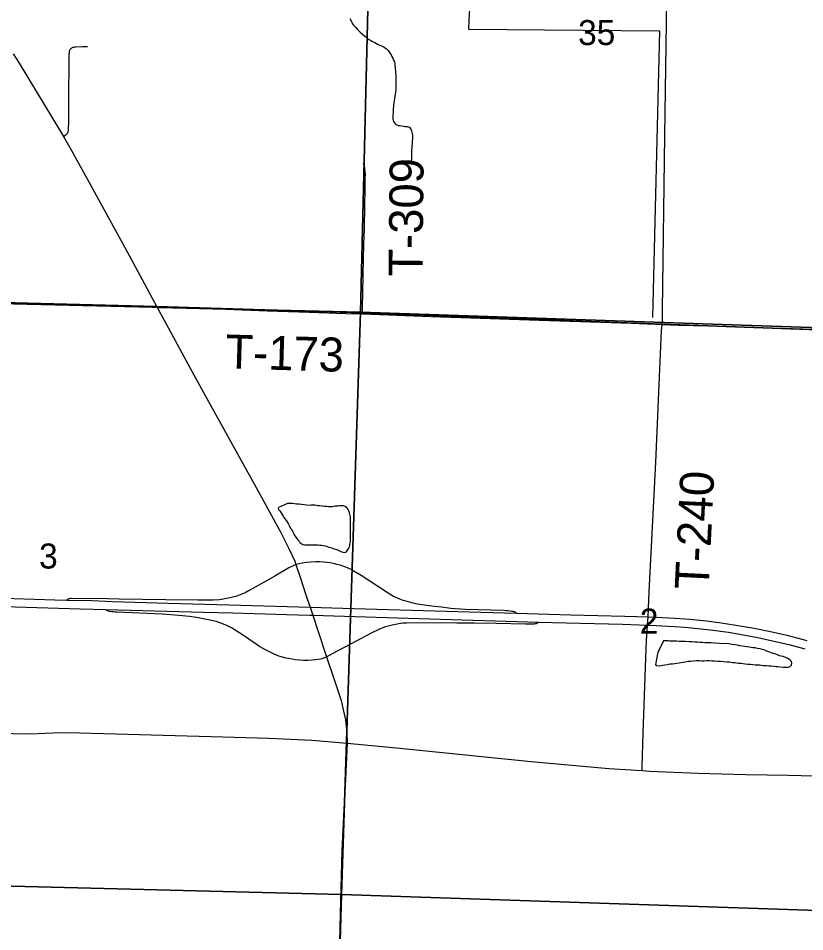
# Model space of a CAD drawing. Extents: x 0 to 68, y 0 to 52.9.
# Drawn here: x 29.418 to 30.689, y 16.814 to 18.289 of the extents above; entities that cross this region are included whole.
import ezdxf

# ---------------------------------------------------------------- set-up
doc = ezdxf.new("R2010")
doc.units = 0
for name, color, linetype in [('Default', 7, 'Continuous'), ('GM_X_County_Road', 7, 'Continuous'), ('GM_X_Minor_Lake', 7, 'Continuous'), ('GM_X_Minor_River', 7, 'Continuous'), ('GM_X_State_Route', 7, 'Continuous'), ('GM_X_Township', 7, 'Continuous'), ('GM_X_Township_Road', 7, 'Continuous'), ('GM_X_Township_Road_Text', 7, 'Continuous')]:
    doc.layers.add(name, color=color, linetype=linetype)

msp = doc.modelspace()

# ---------------------------------------------------------------- linework, layer by layer
at = {"layer": 'Default'}
for points in [[(29.9941, 18.7705), (29.9713, 17.8144), (29.0063, 17.8378), (29.0222, 18.7966)], [(30.9488, 18.7396), (30.9354, 17.7816), (29.9713, 17.8144), (29.9941, 18.7705)], [(28.9884, 17.8384), (29.0063, 17.8378), (29.9713, 17.8144), (29.9405, 16.874), (28.9602, 16.899)], [(29.9713, 17.8144), (30.9354, 17.7816), (30.9018, 16.8419), (29.9405, 16.874)], [(28.9602, 16.899), (29.9405, 16.874), (29.9124, 15.9054), (28.9346, 15.9322)], [(29.9405, 16.874), (30.9018, 16.8419), (30.8795, 15.8743), (29.9124, 15.9054)]]:
    msp.add_lwpolyline(points, close=True, dxfattribs=at)
for points in [[(29.8667, 17.4068), (29.8611, 17.4042), (29.8556, 17.4014), (29.8329, 17.3884), (29.8155, 17.3784), (29.7971, 17.368), (29.7916, 17.3651), (29.7847, 17.3615), (29.7795, 17.3592), (29.7751, 17.3574), (29.7696, 17.3556), (29.7649, 17.3543), (29.7601, 17.353), (29.7548, 17.3519), (29.7498, 17.3509), (29.7436, 17.3502), (29.733, 17.3495), (29.7084, 17.3494), (29.6565, 17.3498), (29.5815, 17.3511), (29.5623, 17.3515), (29.5042, 17.3522), (29.5035, 17.3521), (29.5028, 17.3521), (29.5021, 17.352), (29.5012, 17.3518), (29.5003, 17.3516), (29.4998, 17.3514), (29.4993, 17.3512), (29.4987, 17.3509), (29.498, 17.3506), (29.4974, 17.3501), (29.497, 17.3495)], [(30.2229, 17.3285), (30.2225, 17.3291), (30.222, 17.3296), (30.2215, 17.3299), (30.2207, 17.3303), (30.2196, 17.3306), (30.218, 17.3309), (30.2154, 17.3313), (30.2127, 17.3316), (30.2094, 17.332), (30.2063, 17.3323), (30.2027, 17.3325), (30.1404, 17.3343), (30.1328, 17.3347), (30.1229, 17.3355), (30.1169, 17.3361), (30.1021, 17.3379), (30.0908, 17.3392), (30.0745, 17.3415), (30.0629, 17.3431), (30.0543, 17.3449), (30.0466, 17.3471), (30.0403, 17.349), (30.0345, 17.3512), (30.0245, 17.3555), (30.0159, 17.3607), (29.9721, 17.3895), (29.9623, 17.3953), (29.9561, 17.3989), (29.9476, 17.4025), (29.9381, 17.4058), (29.9332, 17.4072), (29.9298, 17.408), (29.925, 17.409), (29.9219, 17.4096), (29.917, 17.4104), (29.9118, 17.4108), (29.9052, 17.4111), (29.899, 17.4112), (29.8911, 17.4108), (29.884, 17.4101), (29.8772, 17.409), (29.872, 17.4079), (29.8667, 17.4068)], [(29.5602, 17.3342), (29.5608, 17.3335), (29.5616, 17.3329), (29.5623, 17.3325), (29.5637, 17.3321), (29.5659, 17.3317), (29.5699, 17.3311), (29.5718, 17.3309), (29.5749, 17.3306), (29.5774, 17.3304), (29.6516, 17.3276), (29.6778, 17.3254), (29.6952, 17.3234), (29.7061, 17.3218), (29.7172, 17.3199), (29.7286, 17.3177), (29.7377, 17.3154), (29.7468, 17.3125), (29.7558, 17.3087), (29.7644, 17.3041), (29.7806, 17.2939), (29.8008, 17.2801), (29.8088, 17.2748), (29.817, 17.27), (29.8245, 17.2659), (29.8313, 17.2629), (29.8389, 17.2596), (29.8447, 17.2577), (29.8502, 17.2563), (29.8548, 17.2555), (29.866, 17.2536), (29.8729, 17.2531), (29.8792, 17.2528), (29.886, 17.2527), (29.8932, 17.253), (29.8984, 17.2534), (29.9026, 17.254), (29.9065, 17.2547), (29.9093, 17.2553), (29.9138, 17.257), (29.9164, 17.2581)], [(29.9164, 17.2581), (29.9247, 17.2629), (29.9668, 17.2848), (29.9889, 17.2968), (30.0012, 17.3025), (30.0116, 17.3067), (30.0222, 17.3097), (30.0329, 17.3118), (30.0393, 17.3127), (30.0457, 17.3129), (30.0891, 17.3132), (30.1268, 17.3129), (30.1553, 17.3127), (30.1905, 17.3122), (30.2385, 17.3111), (30.2427, 17.3111), (30.2453, 17.3111), (30.2477, 17.3112), (30.2497, 17.3112), (30.2517, 17.3114), (30.2533, 17.3115), (30.2546, 17.3118), (30.2553, 17.3119), (30.2562, 17.3122), (30.2567, 17.3124), (30.2574, 17.3127), (30.2579, 17.3131), (30.2588, 17.314)]]:
    msp.add_lwpolyline(points, dxfattribs=at)
at = {"layer": 'GM_X_County_Road'}
for points in [[(28.9658, 17.1467), (29.0288, 17.1451), (29.1487, 17.1425), (29.2116, 17.1404), (29.3405, 17.1369), (29.4094, 17.1341), (29.4364, 17.1338), (29.4873, 17.1357), (29.5173, 17.1353), (29.7301, 17.1293), (29.823, 17.1267), (29.8582, 17.1249), (29.8926, 17.1231), (29.9495, 17.1187)], [(29.9495, 17.1187), (30.0295, 17.1108), (30.2467, 17.0888), (30.3722, 17.0778), (30.4259, 17.0742)], [(30.4259, 17.0742), (30.438, 17.0734), (30.5159, 17.0702), (30.5938, 17.0678), (30.6628, 17.0666), (30.7437, 17.0647), (30.7616, 17.0634), (30.7765, 17.0612), (30.8058, 17.055), (30.8552, 17.0427), (30.8932, 17.0334), (30.8987, 17.0312), (30.9013, 17.0295), (30.9034, 17.0275), (30.9052, 17.0249)]]:
    msp.add_lwpolyline(points, dxfattribs=at)
at = {"layer": 'GM_X_Minor_Lake'}
for points in [[(29.8387, 17.4992), (29.8383, 17.4981), (29.8387, 17.4959), (29.8409, 17.4937), (29.8431, 17.4904), (29.8449, 17.4879), (29.8463, 17.4853), (29.8474, 17.4831), (29.8493, 17.4805), (29.8515, 17.4776), (29.8533, 17.4746), (29.8547, 17.4721)], [(29.8547, 17.4721), (29.8566, 17.4688), (29.8577, 17.4665), (29.8591, 17.4647), (29.8602, 17.4625), (29.8613, 17.4607), (29.8624, 17.4585), (29.8635, 17.4566), (29.8642, 17.4548), (29.8683, 17.4489), (29.8697, 17.4471), (29.8719, 17.4445), (29.8734, 17.4427), (29.8763, 17.4405), (29.8781, 17.4394), (29.8814, 17.4386), (29.8833, 17.4386), (29.8858, 17.4386), (29.888, 17.439), (29.8906, 17.4389), (29.8943, 17.4389), (29.8968, 17.4389), (29.8998, 17.4389), (29.9027, 17.4389), (29.9053, 17.4385), (29.9082, 17.4382), (29.9111, 17.4378), (29.9144, 17.437), (29.9174, 17.4359), (29.9199, 17.4352), (29.9225, 17.4344), (29.9247, 17.4341), (29.9284, 17.4322), (29.9306, 17.4319), (29.9328, 17.4311), (29.9361, 17.4296), (29.9394, 17.4278), (29.9412, 17.4274), (29.9448, 17.4263), (29.9471, 17.4267), (29.9493, 17.4285), (29.9504, 17.4303), (29.9522, 17.4332), (29.9533, 17.4358), (29.9537, 17.4376), (29.954, 17.4398), (29.9544, 17.442), (29.9548, 17.4442), (29.9548, 17.4534), (29.9552, 17.4563), (29.9552, 17.4589), (29.9552, 17.4615), (29.9552, 17.464), (29.9552, 17.4659), (29.9552, 17.4688), (29.9552, 17.4721), (29.9552, 17.4761), (29.9552, 17.4787), (29.9552, 17.4816), (29.9549, 17.4842), (29.9545, 17.4864), (29.9542, 17.4882), (29.9534, 17.4904), (29.9527, 17.4923), (29.9512, 17.4956), (29.9494, 17.4978), (29.9465, 17.5007), (29.9436, 17.5015), (29.941, 17.5015), (29.9388, 17.5015), (29.937, 17.5015), (29.9344, 17.5011), (29.9322, 17.5011), (29.93, 17.5011), (29.9274, 17.5008), (29.9252, 17.5004), (29.9227, 17.5004), (29.9197, 17.5004), (29.9164, 17.5008), (29.9131, 17.5008), (29.9095, 17.5012), (29.9051, 17.5016), (29.9025, 17.502), (29.8999, 17.5023), (29.8974, 17.5027), (29.8948, 17.5027), (29.8915, 17.5027), (29.8882, 17.5024), (29.8842, 17.5028), (29.8721, 17.5043), (29.8677, 17.5046), (29.8644, 17.505), (29.8611, 17.5054), (29.8581, 17.5054), (29.8556, 17.5054), (29.8534, 17.5054), (29.8387, 17.4992)], [(30.4605, 17.2838), (30.4512, 17.2648), (30.4509, 17.263), (30.4505, 17.26), (30.4498, 17.2571), (30.4494, 17.2542), (30.4486, 17.2513), (30.4483, 17.2476), (30.4475, 17.2458), (30.4486, 17.2439), (30.4545, 17.2435), (30.4571, 17.2439), (30.4596, 17.2446), (30.4626, 17.245), (30.4666, 17.2457), (30.471, 17.2464), (30.475, 17.2468), (30.4787, 17.2471), (30.4824, 17.2478), (30.486, 17.2482), (30.489, 17.2486), (30.4923, 17.2493), (30.4956, 17.25), (30.5007, 17.2507), (30.5048, 17.2511), (30.5092, 17.2514), (30.5139, 17.2518), (30.518, 17.2518), (30.5224, 17.2517), (30.5264, 17.2517), (30.5304, 17.2521), (30.5345, 17.2521), (30.5385, 17.2517), (30.5429, 17.2513), (30.5488, 17.2509), (30.5535, 17.2509), (30.5579, 17.2505), (30.5627, 17.2501), (30.5675, 17.2498), (30.5722, 17.249), (30.5766, 17.2486), (30.5814, 17.2479), (30.5854, 17.2475), (30.5891, 17.2471), (30.5928, 17.2467), (30.5968, 17.246), (30.6012, 17.246), (30.6049, 17.2456), (30.6085, 17.2452), (30.6122, 17.2449), (30.6162, 17.2448), (30.6191, 17.2445), (30.6221, 17.2441), (30.6246, 17.2437), (30.6272, 17.2437), (30.6305, 17.2433), (30.6345, 17.2433), (30.6393, 17.2426), (30.6426, 17.2422), (30.6455, 17.2422), (30.654, 17.241), (30.6562, 17.241), (30.6595, 17.241), (30.662, 17.2414), (30.665, 17.2421), (30.6672, 17.2443), (30.6679, 17.248), (30.6672, 17.2505), (30.6654, 17.2527), (30.6628, 17.2546), (30.6584, 17.2568), (30.6562, 17.2575), (30.6537, 17.2583), (30.6507, 17.259), (30.6478, 17.2598), (30.6449, 17.2609), (30.6423, 17.262), (30.639, 17.2631), (30.6364, 17.2638), (30.6335, 17.2649), (30.6306, 17.2661), (30.6273, 17.2672), (30.6243, 17.2686), (30.6207, 17.2698), (30.6166, 17.2709), (30.6126, 17.2716), (30.6089, 17.2724), (30.6049, 17.2727), (30.5994, 17.2735), (30.595, 17.2739), (30.5913, 17.2746), (30.5881, 17.2754), (30.584, 17.2757), (30.5804, 17.2765), (30.576, 17.2772), (30.5712, 17.278), (30.5661, 17.2787), (30.551, 17.2795)], [(30.551, 17.2795), (30.5437, 17.2799), (30.5378, 17.2803), (30.5327, 17.2807), (30.5279, 17.2807), (30.5235, 17.2811), (30.5191, 17.2811), (30.5155, 17.2815), (30.5111, 17.2818), (30.5067, 17.2819), (30.5015, 17.2822), (30.4964, 17.2826), (30.4902, 17.2826), (30.4861, 17.2827), (30.4817, 17.283), (30.4781, 17.2834), (30.4751, 17.2834), (30.4726, 17.2834), (30.4704, 17.2834), (30.4682, 17.2835), (30.466, 17.2835), (30.4619, 17.2835), (30.4605, 17.2838)]]:
    msp.add_lwpolyline(points, dxfattribs=at)
at = {"layer": 'GM_X_Minor_River'}
for points in [[(30.1496, 18.3393), (30.146, 18.2865)], [(29.9541, 18.2888), (29.9571, 18.2827), (29.9578, 18.2809), (29.9596, 18.2783), (29.9633, 18.2746), (29.9666, 18.2709), (29.9706, 18.2669), (29.9746, 18.2636), (29.9779, 18.2606), (29.9805, 18.2584), (29.9827, 18.2566), (29.9849, 18.2551), (29.9871, 18.2536), (29.9893, 18.2522), (29.9915, 18.2511), (29.9941, 18.25), (29.9973, 18.2485), (29.9999, 18.247), (30.0025, 18.2455), (30.005, 18.2444), (30.0076, 18.2433), (30.0094, 18.2422), (30.0113, 18.2411), (30.0131, 18.2396), (30.0157, 18.2371), (30.0171, 18.2352), (30.0193, 18.2323), (30.0208, 18.2301), (30.0219, 18.2275), (30.0233, 18.2246), (30.0244, 18.2216), (30.0259, 18.2187), (30.0266, 18.2158), (30.0273, 18.2073), (30.0277, 18.204), (30.0277, 18.2004), (30.028, 18.1978), (30.028, 18.1945), (30.0284, 18.1912), (30.0284, 18.1875), (30.0284, 18.1831), (30.028, 18.1787), (30.028, 18.174), (30.0276, 18.1699), (30.0272, 18.1663), (30.0269, 18.163), (30.0261, 18.16), (30.0254, 18.1556), (30.025, 18.1523), (30.0246, 18.1494), (30.0246, 18.1465), (30.0242, 18.1435), (30.0242, 18.141), (30.0242, 18.1388), (30.0239, 18.1362), (30.0235, 18.1336), (30.0235, 18.1311), (30.0235, 18.1292), (30.0235, 18.1263), (30.0238, 18.1245), (30.0246, 18.1226), (30.026, 18.1201), (30.0275, 18.1182), (30.03, 18.1168), (30.0322, 18.116), (30.0348, 18.116), (30.0377, 18.1153), (30.041, 18.1149), (30.0429, 18.1145), (30.0447, 18.1145), (30.0465, 18.1141), (30.0484, 18.1138), (30.0506, 18.113), (30.0528, 18.109), (30.0535, 18.1071), (30.0542, 18.1053), (30.0549, 18.1024), (30.0553, 18.0998), (30.0553, 18.0972), (30.0553, 18.0943), (30.0546, 18.0899), (30.0545, 18.0862), (30.0542, 18.0829), (30.0542, 18.0793), (30.0538, 18.076), (30.0538, 18.0723), (30.0538, 18.069), (30.0534, 18.0661), (30.0534, 18.0635), (30.0534, 18.061), (30.053, 18.0591), (30.053, 18.0569), (30.0526, 18.0562)], [(30.146, 18.2865), (30.1454, 18.2716), (30.4543, 18.2691), (30.443, 17.806)]]:
    msp.add_lwpolyline(points, dxfattribs=at)
at = {"layer": 'GM_X_State_Route'}
for points in [[(29.4101, 18.2319), (29.4197, 18.2166), (29.4617, 18.1474), (29.485, 18.1089), (29.4912, 18.0984), (29.5017, 18.0804), (29.5321, 18.0252), (29.548, 17.9963), (29.5899, 17.9201), (29.6185, 17.8673), (29.643, 17.8222), (29.6543, 17.8014), (29.6927, 17.7301), (29.7174, 17.6846), (29.789, 17.5555)], [(29.789, 17.5555), (29.7933, 17.5479), (29.8398, 17.4634)], [(29.8398, 17.4634), (29.8417, 17.46), (29.855, 17.4339), (29.8649, 17.4123), (29.8667, 17.4068), (29.8747, 17.3836), (29.882, 17.3611), (29.8852, 17.3517)], [(27.8875, 17.3829), (27.9964, 17.3796), (28.078, 17.3771), (28.138, 17.3755), (28.2514, 17.3727), (28.3623, 17.3694), (28.5811, 17.363), (28.668, 17.3605), (28.7309, 17.3589), (28.8868, 17.3541), (28.972, 17.3517), (29.0636, 17.3489), (29.2554, 17.3433), (29.3962, 17.3391), (29.5186, 17.3357), (29.5602, 17.3342), (29.7169, 17.3301), (29.7649, 17.329), (29.8518, 17.3263), (29.8892, 17.3252)], [(29.3128, 17.3551), (29.4773, 17.3498), (29.497, 17.3495), (29.5375, 17.3487), (29.5707, 17.3473), (29.6603, 17.3447), (29.759, 17.3418), (29.8897, 17.338), (29.9602, 17.336), (30.1282, 17.3313), (30.2229, 17.3285), (30.3111, 17.3258), (30.3981, 17.3237), (30.4357, 17.3225), (30.4491, 17.3221), (30.4791, 17.3206), (30.503, 17.3187), (30.5299, 17.3159), (30.5508, 17.3133), (30.5775, 17.3092), (30.6071, 17.3041), (30.6336, 17.2987), (30.6599, 17.2927), (30.6919, 17.2845)], [(29.8852, 17.3517), (29.8897, 17.338), (29.894, 17.325), (29.9027, 17.2987), (29.9164, 17.2581), (29.9287, 17.2212), (29.9351, 17.2017), (29.9398, 17.1875), (29.9428, 17.175), (29.9455, 17.163), (29.9468, 17.156)], [(29.8892, 17.3252), (29.894, 17.325), (30.0136, 17.3216), (30.1005, 17.3189), (30.2588, 17.314), (30.3942, 17.3105), (30.4349, 17.3091), (30.4488, 17.3086), (30.4788, 17.307), (30.4943, 17.3058), (30.506, 17.3048), (30.5359, 17.3016), (30.5655, 17.2975), (30.5924, 17.2931), (30.6132, 17.289), (30.6366, 17.284), (30.6633, 17.2778), (30.6889, 17.2711)], [(29.9468, 17.156), (29.9477, 17.1509), (29.9491, 17.1362), (29.9495, 17.1187), (29.9467, 17.0608)], [(29.9467, 17.0608), (29.9443, 17.0118), (29.9413, 16.9447), (29.939, 16.8637), (29.9369, 16.7767)]]:
    msp.add_lwpolyline(points, dxfattribs=at)
at = {"layer": 'GM_X_Township'}
for points in [[(31.3735, 17.7671), (31.0263, 17.7766), (30.9331, 17.7779), (30.4577, 17.7952), (29.9734, 17.8135), (29.642, 17.8239), (28.9971, 17.8406), (28.5162, 17.8494), (28.0383, 17.8644), (28.0252, 17.8646), (27.3046, 17.882)], [(27.3046, 17.882), (28.0252, 17.8646), (28.0383, 17.8644), (28.5162, 17.8494), (28.9971, 17.8406), (29.642, 17.8239), (29.9734, 17.8135), (30.4577, 17.7952), (30.9331, 17.7779), (30.9135, 17.1991), (30.9077, 17.017), (30.8985, 16.6023), (30.8927, 16.3623), (30.8688, 15.3927), (30.8528, 14.9106), (30.8428, 14.4289), (30.8361, 14.1085)]]:
    msp.add_lwpolyline(points, dxfattribs=at)
at = {"layer": 'GM_X_Township_Road'}
for points in [[(30.4583, 17.7946), (30.4588, 17.7999), (30.4592, 17.8179), (30.463, 18.0998), (30.4659, 18.3188), (30.4659, 18.3728), (30.468, 18.4748), (30.4685, 18.4929), (30.47, 18.5017), (30.472, 18.5073), (30.4749, 18.5126), (30.4818, 18.5224), (30.4845, 18.5277), (30.4862, 18.5334), (30.4873, 18.5423), (30.4885, 18.7523), (30.4886, 18.7571)], [(29.4912, 18.0984), (29.4939, 18.1001), (29.4955, 18.1012), (29.4963, 18.1018), (29.4971, 18.1027), (29.4975, 18.1032), (29.4982, 18.1041), (29.4985, 18.1047), (29.4989, 18.1056), (29.4992, 18.1064), (29.4994, 18.1075), (29.4996, 18.1089), (29.4997, 18.1107), (29.4997, 18.1128), (29.4999, 18.1195), (29.4999, 18.123), (29.4999, 18.1358), (29.5002, 18.1572), (29.5002, 18.174), (29.5005, 18.2076), (29.5008, 18.2316), (29.5009, 18.2333), (29.501, 18.234), (29.5011, 18.2351), (29.5012, 18.2358), (29.5015, 18.237), (29.5018, 18.2377), (29.5022, 18.2385), (29.5028, 18.2395), (29.5036, 18.2402), (29.5042, 18.2408), (29.505, 18.2413), (29.5059, 18.2418), (29.507, 18.2422), (29.5082, 18.2425), (29.5095, 18.2428), (29.5111, 18.2429), (29.5219, 18.2434), (29.5303, 18.2437)], [(29.9742, 17.8116), (29.9743, 17.8165), (29.9744, 17.8221), (29.9755, 17.8717), (29.9761, 17.9029), (29.9762, 17.9071), (29.9766, 17.9173), (29.9768, 17.9245), (29.9772, 17.9359), (29.9776, 17.9491), (29.9782, 17.9881), (29.9786, 18.0127), (29.9789, 18.0319), (29.979, 18.0365), (29.9786, 18.0425), (29.9784, 18.0453), (29.978, 18.0478), (29.9771, 18.0509), (29.9761, 18.0545)], [(29.643, 17.8222), (29.6679, 17.8217), (29.7536, 17.8192), (29.8211, 17.8165), (29.8882, 17.8144), (29.9473, 17.8123), (29.9742, 17.8116)], [(29.9742, 17.8116), (30.0162, 17.81), (30.0845, 17.8077), (30.1496, 17.8054), (30.2116, 17.8031), (30.2761, 17.8009), (30.3428, 17.7988), (30.4089, 17.7966), (30.4477, 17.7952), (30.4583, 17.7946)], [(30.4377, 17.3631), (30.4481, 17.5722), (30.4575, 17.785), (30.4583, 17.7946)], [(30.4583, 17.7946), (30.4854, 17.7936), (30.5552, 17.7917), (30.6178, 17.7897), (30.7031, 17.7869), (30.7441, 17.7857), (30.8026, 17.7832), (30.9384, 17.7784)], [(30.4357, 17.3225), (30.4377, 17.3631)], [(30.4349, 17.3091), (30.4357, 17.3225)], [(30.4323, 17.2562), (30.4334, 17.2845), (30.4349, 17.3091)], [(30.4259, 17.0742), (30.4261, 17.0807), (30.4278, 17.1346), (30.4323, 17.2562)]]:
    msp.add_lwpolyline(points, dxfattribs=at)

# ---------------------------------------------------------------- texts
at = {"layer": 'Default'}
for s, height, p in [('35', 0.04038, (30.3227, 18.2458)), ('3', 0.0404, (29.452, 17.4005)), ('2', 0.0404, (30.4223, 17.2955))]:
    msp.add_text(s, height=height, rotation=0, dxfattribs=at).set_placement(p)
at = {"layer": 'GM_X_Township_Road_Text'}
for s, rotation, p in [('T-309', 89.4372, (30.0713, 17.8716)), ('T-173', 358.3152, (29.7523, 17.7238)), ('T-240', 87.1941, (30.5334, 17.3656))]:
    msp.add_text(s, height=0.05481, rotation=rotation, dxfattribs=at).set_placement(p)

doc.saveas('drawing.dxf')
